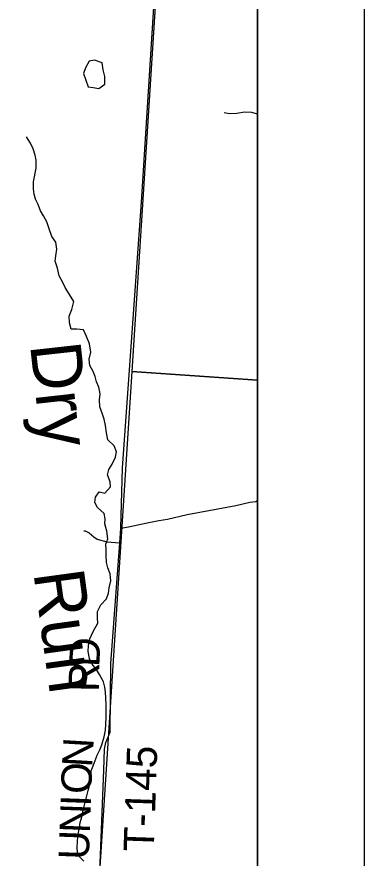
# Model space of a CAD drawing. Extents: x 0 to 42.5, y 0 to 22.
# Drawn here: x 8.674 to 9, y 16.629 to 17.417 of the extents above; entities that cross this region are included whole.
import ezdxf

# ---------------------------------------------------------------- set-up
doc = ezdxf.new("R2010")
doc.units = 0
for name, color, linetype in [('GM_X_Interchange_Ramps', 7, 'Continuous'), ('GM_X_Minor_Lake', 7, 'Continuous'), ('GM_X_Minor_River', 7, 'Continuous'), ('GM_X_Minor_River_Text', 7, 'Continuous'), ('GM_X_Township_Road', 7, 'Continuous'), ('GM_X_Township_Road_Text', 7, 'Continuous'), ('GM_X_Unincorporated', 7, 'Continuous'), ('SH_Cut_Line', 7, 'Continuous'), ('SH_Data', 7, 'Continuous')]:
    doc.layers.add(name, color=color, linetype=linetype)

msp = doc.modelspace()

# ---------------------------------------------------------------- linework, layer by layer
at = {"layer": 'GM_X_Interchange_Ramps'}
msp.add_lwpolyline([(8.9, 15.53758), (8.9, 19.05381), (8.80207, 19.06082), (8.79715, 19.06117), (8.45529, 19.08562), (8.42249, 18.59682), (8.4216, 18.58362), (8.41233, 18.47844), (8.38323, 18.14846), (8.33786, 17.63394), (8.30797, 17.29222), (8.30866, 17.28459), (8.30841, 17.27648), (8.30737, 17.26941), (8.29023, 17.08765), (8.28773, 17.0646), (8.28228, 16.99116), (8.27401, 16.89234), (8.25723, 16.70556), (8.24802, 16.59431), (8.24781, 16.59008), (8.17933, 15.79111)], dxfattribs=at)
at = {"layer": 'GM_X_Minor_Lake'}
for p, q in [((8.74229, 17.37561), (8.73888, 17.36954)), ((8.74722, 17.37656), (8.74229, 17.37561)), ((8.75443, 17.3741), (8.74722, 17.37656)), ((8.75472, 17.37204), (8.75443, 17.3741)), ((8.73888, 17.36954), (8.7368, 17.36404)), ((8.75538, 17.36747), (8.75472, 17.37204)), ((8.7569, 17.36121), (8.75538, 17.36747)), ((8.7368, 17.36404), (8.74117, 17.35172)), ((8.75671, 17.35419), (8.7569, 17.36121)), ((8.74117, 17.35172), (8.74591, 17.35096)), ((8.74591, 17.35096), (8.75121, 17.35021)), ((8.75121, 17.35021), (8.75671, 17.35419))]:
    msp.add_line(p, q, dxfattribs=at)
at = {"layer": 'GM_X_Minor_River'}
for p, q in [((8.74253, 16.69746), (8.74415, 16.70818)), ((8.74117, 16.69254), (8.74253, 16.69746)), ((8.73962, 16.68648), (8.74117, 16.69254)), ((8.73669, 16.67417), (8.73962, 16.68648)), ((8.73551, 16.66887), (8.73669, 16.67417)), ((8.73376, 16.66281), (8.73551, 16.66887)), ((8.73179, 16.65163), (8.73316, 16.65788)), ((8.73316, 16.65788), (8.73376, 16.66281)), ((8.73118, 16.64538), (8.73179, 16.65163)), ((8.73094, 16.63874), (8.73118, 16.64538)), ((8.73165, 16.6321), (8.73094, 16.63874)), ((8.7371, 16.62657), (8.73165, 16.6321))]:
    msp.add_line(p, q, dxfattribs=at)
for points in [[(8.9, 17.32587), (8.89451, 17.32763), (8.88788, 17.32803), (8.88067, 17.32673), (8.87384, 17.32638), (8.86873, 17.32735)], [(8.6924, 17.28289), (8.69166, 17.28763), (8.6896, 17.29371), (8.68716, 17.29884), (8.68339, 17.30492)], [(8.74415, 16.70818), (8.74416, 16.71091), (8.74607, 16.71583), (8.74952, 16.72568), (8.7522, 16.7306), (8.75392, 16.73553), (8.75623, 16.74291), (8.75739, 16.74898), (8.75779, 16.75448), (8.75801, 16.76168), (8.75822, 16.76642), (8.75824, 16.77287), (8.7577, 16.77932), (8.75753, 16.78463), (8.75698, 16.78956), (8.75568, 16.7945), (8.75191, 16.80134), (8.7489, 16.80609), (8.74512, 16.81085), (8.74249, 16.81617), (8.74119, 16.82281), (8.74159, 16.82831), (8.74275, 16.83456), (8.74581, 16.84157), (8.7504, 16.84933), (8.74985, 16.85426), (8.74987, 16.86014), (8.75312, 16.86657), (8.75845, 16.87224), (8.76018, 16.87736), (8.76077, 16.88228), (8.7625, 16.88892), (8.76177, 16.89556), (8.75971, 16.90125), (8.7584, 16.90619), (8.75804, 16.91283), (8.75807, 16.91814), (8.7579, 16.92326), (8.75981, 16.92837), (8.7587, 16.93539), (8.75683, 16.94223), (8.75723, 16.94716), (8.7563, 16.9519), (8.74988, 16.95762), (8.74744, 16.96237), (8.74821, 16.96729), (8.75165, 16.97221), (8.75676, 16.97124), (8.76228, 16.97691), (8.76173, 16.98166), (8.75948, 16.98811), (8.76064, 16.99323), (8.76369, 16.99834), (8.76694, 17.00477), (8.76772, 17.00989), (8.76566, 17.0154), (8.7598, 17.02111), (8.75831, 17.02756), (8.75739, 17.03439), (8.75609, 17.04028), (8.75459, 17.04521), (8.75215, 17.05186), (8.7518, 17.0585), (8.75258, 17.06419), (8.75109, 17.07026), (8.74902, 17.0752), (8.74791, 17.08032), (8.74584, 17.08507), (8.74283, 17.09077), (8.74209, 17.09666), (8.74383, 17.1031), (8.74234, 17.11107), (8.73952, 17.11772), (8.7367, 17.12399), (8.73045, 17.12458), (8.72533, 17.1246), (8.72365, 17.13048), (8.72329, 17.13674), (8.72597, 17.14299), (8.7279, 17.15057), (8.72375, 17.15703), (8.7198, 17.16369), (8.71735, 17.16844), (8.71415, 17.17471), (8.71248, 17.18192), (8.71042, 17.18838), (8.71082, 17.1933), (8.71198, 17.19956), (8.71106, 17.2062), (8.70729, 17.21133), (8.70466, 17.21855), (8.70241, 17.2252), (8.69921, 17.23071), (8.69639, 17.23546), (8.69432, 17.24154), (8.69188, 17.24629), (8.69057, 17.25122), (8.68983, 17.25616), (8.69005, 17.26279), (8.69237, 17.2753), (8.6924, 17.28289)]]:
    msp.add_lwpolyline(points, dxfattribs=at)
at = {"layer": 'GM_X_Township_Road'}
for points in [[(8.8329, 16.54439), (8.75198, 16.60851), (8.7558, 16.71165), (8.75666, 16.73142), (8.75777, 16.73769), (8.76191, 16.7474), (8.76238, 16.81144), (8.77085, 16.92466), (8.77199, 16.93824), (8.77352, 16.99486), (8.79121, 17.24348), (8.80609, 17.48076), (8.80612, 17.48125)], [(8.77199, 16.93824), (8.77915, 16.93962), (8.79649, 16.94344), (8.80738, 16.94557), (8.81546, 16.94686), (8.83416, 16.95096), (8.85436, 16.955), (8.87951, 16.95949), (8.89275, 16.96263), (8.89833, 16.96334), (8.9, 16.96431)], [(8.73727, 16.93596), (8.73846, 16.93588), (8.74208, 16.93401), (8.74641, 16.93027), (8.7498, 16.92805), (8.75868, 16.92559), (8.77085, 16.92466)]]:
    msp.add_lwpolyline(points, dxfattribs=at)
at = {"layer": 'GM_X_Unincorporated'}
for points in [[(8.9, 17.07703), (8.9, 17.59215), (8.81502, 17.59822), (8.78214, 17.08517)], [(8.9, 16.56221), (8.9, 17.07703), (8.78214, 17.08517), (8.74916, 16.5726)]]:
    msp.add_lwpolyline(points, close=True, dxfattribs=at)
at = {"layer": 'SH_Cut_Line'}
msp.add_lwpolyline([(8.9, 14.1), (8.9, 19.05381), (8.80207, 19.06082), (8.79715, 19.06117), (8.45529, 19.08562), (8.42249, 18.59682), (8.4216, 18.58362), (8.41233, 18.47844), (8.38323, 18.14846), (8.33786, 17.63394), (8.30797, 17.29222), (8.30866, 17.28459), (8.30841, 17.27648), (8.30737, 17.26941), (8.29023, 17.08765), (8.28773, 17.0646), (8.28228, 16.99116), (8.27401, 16.89234), (8.25723, 16.70556), (8.24802, 16.59431), (8.24781, 16.59008), (8.17933, 15.79111)], dxfattribs=at)
at = {"layer": 'SH_Data'}
for p, q in [((9, 21), (9, 14)), ((8.9, 20.9), (8.9, 14.1))]:
    msp.add_line(p, q, dxfattribs=at)

# ---------------------------------------------------------------- texts
at = {"layer": 'GM_X_Minor_River_Text'}
for s, rotation, p in [('Dry ', 276.36674, (8.68664, 17.11011)), ('Run', 277.80336, (8.68979, 16.89658))]:
    msp.add_text(s, height=0.047349, rotation=rotation, dxfattribs=at).set_placement(p)
at = {"layer": 'GM_X_Township_Road_Text'}
for s, height, rotation, p in [('D', 0.02841, 86.72701, (8.75156, 16.80787)), ('R', 0.02841, 89.55896, (8.75139, 16.78491)), ('N', 0.02841, 86.58839, (8.74492, 16.71386)), ('T-145', 0.028409, 88.03529, (8.80269, 16.63499)), ('O', 0.02841, 87.91584, (8.74402, 16.68905)), ('I', 0.02841, 87.93832, (8.7436, 16.67739)), ('N', 0.02841, 87.93767, (8.7427, 16.65241)), ('U', 0.02841, 87.93768, (8.7418, 16.62742))]:
    msp.add_text(s, height=height, rotation=rotation, dxfattribs=at).set_placement(p)

doc.saveas('drawing.dxf')
